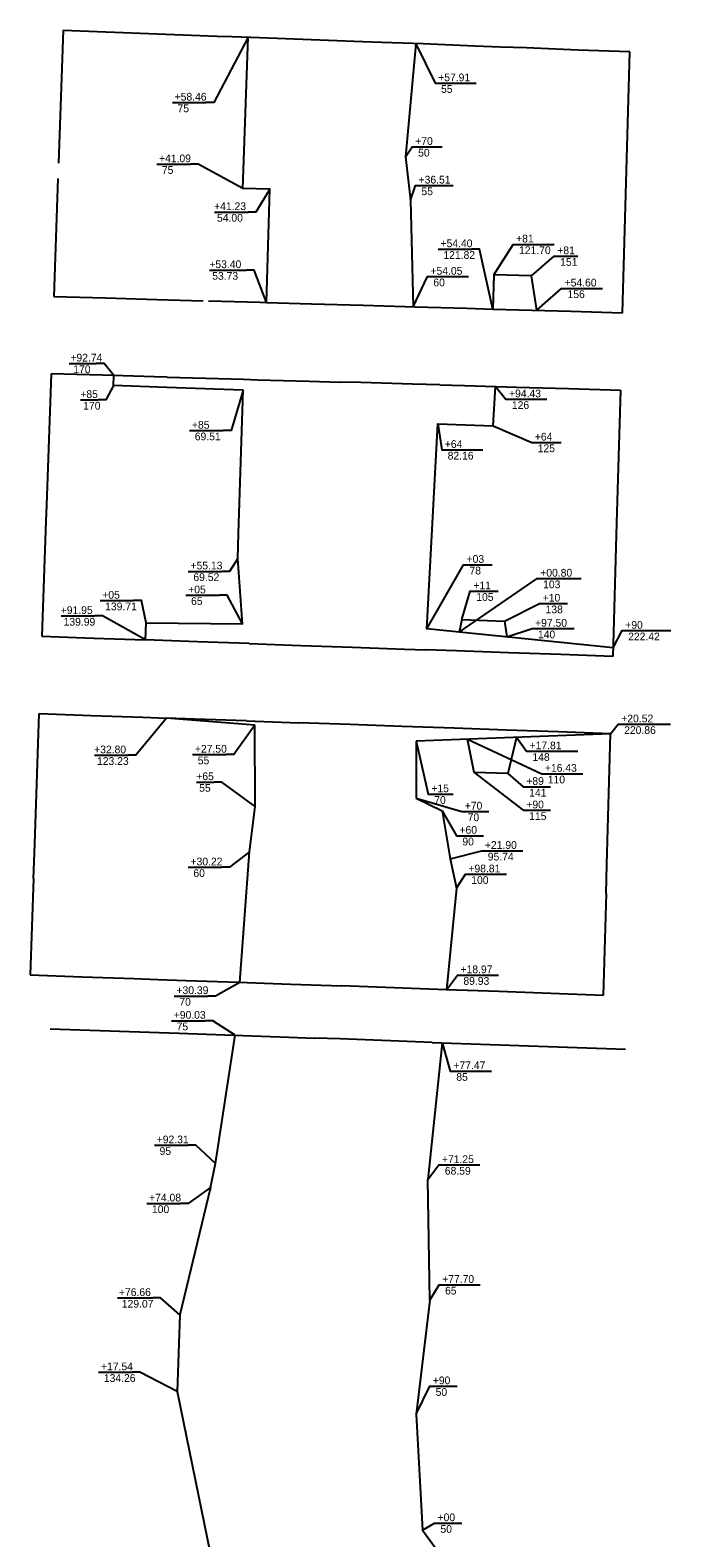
# Model space of a CAD drawing. Extents: x 979729 to 993523, y 1834148 to 1845433.
# Drawn here: x 992244 to 992740, y 1841951 to 1843120 of the extents above; entities that cross this region are included whole.
import ezdxf

# ---------------------------------------------------------------- set-up
doc = ezdxf.new("R2010")
doc.units = 0
for name, color, linetype in [('51', 7, 'Continuous'), ('53', 7, 'Continuous'), ('R_Draft', 7, 'Continuous'), ('S_EXIST_ROW', 7, 'Continuous')]:
    doc.layers.add(name, color=color, linetype=linetype)

msp = doc.modelspace()

# ---------------------------------------------------------------- linework, layer by layer
at = {"layer": '51'}
for p, q in [((992542.5, 1843109.9), (992534.5, 1843022.2)), ((992534.5, 1843022.2), (992538.3, 1842988.6)), ((992308.2, 1842844.8), (992308.5, 1842852.6)), ((992349.5, 1842843.4), (992308.2, 1842844.8)), ((992408.7, 1842841.4), (992349.5, 1842843.4)), ((992405.2, 1842730.1), (992408.7, 1842841.4)), ((992418, 1842518.5), (992417.7, 1842581.6)), ((992693.5, 1842574.8), (992542.7, 1842569.2)), ((992542.7, 1842569.2), (992542.9, 1842524.8)), ((992693.5, 1842574.8), (992693.5, 1842574.8)), ((992693.5, 1842574.8), (992693.5, 1842574.8)), ((992542.9, 1842524.8), (992563, 1842515.1)), ((992418, 1842518.5), (992418, 1842518.5)), ((992418, 1842518.5), (992418, 1842518.5)), ((992574.1, 1842455.1), (992566.3, 1842376.4)), ((992387.4, 1842241.6), (992402.6, 1842341.1)), ((992563, 1842335.3), (992551.9, 1842229.2)), ((992383.4, 1842223.1), (992387.4, 1842241.6)), ((992383.4, 1842223.1), (992359.5, 1842124.3)), ((992359.5, 1842124.3), (992357.5, 1842065)), ((992357.5, 1842065), (992383.4, 1841938.6))]:
    msp.add_line(p, q, dxfattribs=at)
for points in [[(992426.8, 1842909.2), (992429.5, 1842997), (992408.5, 1842997.6), (992412.6, 1843114.9)], [(992542.5, 1843109.9), (992542.5, 1843109.9)], [(992538.3, 1842988.6), (992540.5, 1842906)], [(992695.4, 1842641.6), (992551.2, 1842656.1), (992559.5, 1842815.2), (992602.4, 1842813.7), (992604.4, 1842844.1)], [(992333, 1842647.6), (992333.5, 1842661), (992408.2, 1842660), (992404.6, 1842710.8), (992405.2, 1842730.1)], [(992417.7, 1842581.6), (992349.4, 1842587)], [(992406.1, 1842382.1), (992413.5, 1842483.3), (992418, 1842518.5)], [(992563, 1842515.1), (992569.3, 1842477.8), (992574.1, 1842455.1)], [(992553.3, 1842135.6), (992551.9, 1842229.2)], [(992553.3, 1842135.6), (992542.9, 1842047.2), (992547.7, 1841957.3), (992563.9, 1841935.1)]]:
    msp.add_lwpolyline(points, dxfattribs=at)
at = {"layer": '53'}
for p, q in [((992578.3, 1842663.5), (992576.1, 1842653.6)), ((992578.3, 1842663.5), (992611.2, 1842662.1)), ((992611.2, 1842662.1), (992613.1, 1842649.9))]:
    msp.add_line(p, q, dxfattribs=at)
for points in [[(992636.4, 1842903.2), (992632.3, 1842929.8), (992603.1, 1842930.8), (992602.3, 1842904.2)], [(992620.7, 1842572.1), (992613.8, 1842544), (992587.8, 1842544.8), (992582.7, 1842570.7)]]:
    msp.add_lwpolyline(points, dxfattribs=at)
at = {"layer": 'R_Draft'}
for p, q in [((992563.5, 1843079.3), (992589.3, 1843079.3)), ((992353.9, 1843064.3), (992379.9, 1843064.3)), ((992545.8, 1843029.9), (992563.1, 1843029.9)), ((992341.7, 1843016.5), (992367.8, 1843016.5)), ((992548.4, 1843000), (992571.4, 1843000)), ((992386.5, 1842979.4), (992412.6, 1842979.4)), ((992623.9, 1842954.3), (992649.8, 1842954.3)), ((992559.9, 1842950.6), (992586, 1842950.6)), ((992655.8, 1842945.2), (992668.1, 1842945.2)), ((992382.5, 1842934.4), (992411.3, 1842934.4)), ((992557.5, 1842929.3), (992583.4, 1842929.3)), ((992661.5, 1842920.2), (992687.3, 1842920.2)), ((992273.9, 1842862), (992294.9, 1842862)), ((992282.6, 1842833.7), (992296.3, 1842833.7)), ((992618.4, 1842834.2), (992644.2, 1842834.2)), ((992367.2, 1842809.9), (992393.3, 1842809.9)), ((992568.6, 1842795), (992594.5, 1842795)), ((992638.4, 1842800.7), (992655.3, 1842800.7)), ((992366.1, 1842700.8), (992392.2, 1842700.8)), ((992585.6, 1842705.9), (992601.7, 1842705.9)), ((992590.8, 1842685.4), (992606.3, 1842685.4)), ((992642.6, 1842695.2), (992670.7, 1842695.2)), ((992297.8, 1842678.1), (992323.8, 1842678.1)), ((992364.3, 1842682.2), (992390.3, 1842682.2)), ((992644.5, 1842675.8), (992660, 1842675.8)), ((992267.6, 1842666.2), (992293.6, 1842666.2)), ((992638.7, 1842656.4), (992665.3, 1842656.4)), ((992708.5, 1842654.8), (992740.2, 1842654.8)), ((992705.4, 1842582.2), (992739.9, 1842582.2)), ((992293.5, 1842558.2), (992319.6, 1842558.2)), ((992369.5, 1842558.7), (992395.6, 1842558.7)), ((992634.3, 1842561.3), (992668.1, 1842561.3)), ((992646.3, 1842543.9), (992672.1, 1842543.9)), ((992372.6, 1842537.4), (992386.2, 1842537.4)), ((992631.8, 1842533.7), (992646.9, 1842533.7)), ((992558.2, 1842528), (992571.4, 1842528)), ((992584.1, 1842514.6), (992599.2, 1842514.6)), ((992631.8, 1842515.5), (992646.9, 1842515.5)), ((992580, 1842495.8), (992595.1, 1842495.8)), ((992599.7, 1842484.1), (992625.5, 1842484.1)), ((992366.1, 1842471.3), (992392.2, 1842471.3)), ((992587, 1842465.9), (992612.8, 1842465.9)), ((992580.8, 1842387.7), (992606.7, 1842387.7)), ((992355.2, 1842371.5), (992381.2, 1842371.5)), ((992353.2, 1842352.4), (992379.2, 1842352.4)), ((992575.3, 1842313.3), (992601.2, 1842313.3)), ((992340, 1842255.8), (992366, 1842255.8)), ((992566.4, 1842240.5), (992592.2, 1842240.5)), ((992334, 1842210.7), (992360.1, 1842210.7)), ((992566.6, 1842147.6), (992592.4, 1842147.6)), ((992311.4, 1842137.4), (992338.7, 1842137.4)), ((992296.7, 1842079.8), (992322.7, 1842079.8)), ((992559.3, 1842069), (992574.5, 1842069)), ((992563, 1841962.8), (992578.1, 1841962.8))]:
    msp.add_line(p, q, dxfattribs=at)
for points in [[(992412.6, 1843114.9), (992385.9, 1843064.3), (992379.9, 1843064.3)], [(992542.5, 1843109.9), (992557.5, 1843079.3), (992563.5, 1843079.3)], [(992534.5, 1843022.2), (992539.8, 1843029.9), (992545.8, 1843029.9)], [(992408.5, 1842997.6), (992373.8, 1843016.5), (992367.8, 1843016.5)], [(992538.3, 1842988.6), (992542.4, 1843000), (992548.4, 1843000)], [(992429.5, 1842997), (992418.6, 1842979.4), (992412.6, 1842979.4)], [(992603.1, 1842930.8), (992617.9, 1842954.3), (992623.9, 1842954.3)], [(992602.3, 1842904.2), (992592, 1842950.6), (992586, 1842950.6)], [(992632.3, 1842929.8), (992649.8, 1842945.2), (992655.8, 1842945.2)], [(992426.8, 1842909.2), (992417.3, 1842934.4), (992411.3, 1842934.4)], [(992540.5, 1842906), (992551.5, 1842929.3), (992557.5, 1842929.3)], [(992636.4, 1842903.2), (992655.5, 1842920.2), (992661.5, 1842920.2)], [(992308.5, 1842852.6), (992300.9, 1842862), (992294.9, 1842862)], [(992308.2, 1842844.8), (992302.3, 1842833.7), (992296.3, 1842833.7)], [(992408.7, 1842841.4), (992399.3, 1842809.9), (992393.3, 1842809.9)], [(992604.4, 1842844.1), (992612.4, 1842834.2), (992618.4, 1842834.2)], [(992559.5, 1842815.2), (992562.6, 1842795), (992568.6, 1842795)], [(992602.4, 1842813.7), (992632.4, 1842800.7), (992638.4, 1842800.7)], [(992404.6, 1842710.8), (992398.2, 1842700.8), (992392.2, 1842700.8)], [(992551.2, 1842656.1), (992579.6, 1842705.9), (992585.6, 1842705.9)], [(992576.1, 1842653.6), (992636.6, 1842695.2), (992642.6, 1842695.2)], [(992578.3, 1842663.5), (992584.8, 1842685.4), (992590.8, 1842685.4)], [(992333.5, 1842661), (992329.8, 1842678.1), (992323.8, 1842678.1)], [(992408.2, 1842660), (992396.3, 1842682.2), (992390.3, 1842682.2)], [(992611.2, 1842662.1), (992638.5, 1842675.8), (992644.5, 1842675.8)], [(992333, 1842647.6), (992299.6, 1842666.2), (992293.6, 1842666.2)], [(992613.1, 1842649.9), (992632.7, 1842656.4), (992638.7, 1842656.4)], [(992695.4, 1842641.6), (992702.5, 1842654.8), (992708.5, 1842654.8)], [(992349.4, 1842587), (992325.6, 1842558.2), (992319.6, 1842558.2)], [(992417.7, 1842581.6), (992401.6, 1842558.7), (992395.6, 1842558.7)], [(992693.5, 1842574.8), (992699.4, 1842582.2), (992705.4, 1842582.2)], [(992542.7, 1842569.2), (992552.2, 1842528), (992558.2, 1842528)], [(992582.7, 1842570.7), (992640.3, 1842543.9), (992646.3, 1842543.9)], [(992620.7, 1842572.1), (992628.3, 1842561.3), (992634.3, 1842561.3)], [(992587.8, 1842544.8), (992625.8, 1842515.5), (992631.8, 1842515.5)], [(992613.8, 1842544), (992625.8, 1842533.7), (992631.8, 1842533.7)], [(992418, 1842518.5), (992392.2, 1842537.4), (992386.2, 1842537.4)], [(992542.9, 1842524.8), (992578.1, 1842514.6), (992584.1, 1842514.6)], [(992563, 1842515.1), (992574, 1842495.8), (992580, 1842495.8)], [(992413.5, 1842483.3), (992398.2, 1842471.3), (992392.2, 1842471.3)], [(992569.3, 1842477.8), (992593.7, 1842484.1), (992599.7, 1842484.1)], [(992574.1, 1842455.1), (992581, 1842465.9), (992587, 1842465.9)], [(992406.1, 1842382.1), (992387.2, 1842371.5), (992381.2, 1842371.5)], [(992566.3, 1842376.4), (992574.8, 1842387.7), (992580.8, 1842387.7)], [(992402.6, 1842341.1), (992385.2, 1842352.4), (992379.2, 1842352.4)], [(992563, 1842335.3), (992569.3, 1842313.3), (992575.3, 1842313.3)], [(992387.4, 1842241.6), (992372, 1842255.8), (992366, 1842255.8)], [(992551.9, 1842229.2), (992560.4, 1842240.5), (992566.4, 1842240.5)], [(992383.4, 1842223.1), (992366.1, 1842210.7), (992360.1, 1842210.7)], [(992553.3, 1842135.6), (992560.6, 1842147.6), (992566.6, 1842147.6)], [(992359.5, 1842124.3), (992344.7, 1842137.4), (992338.7, 1842137.4)], [(992357.5, 1842065), (992328.7, 1842079.8), (992322.7, 1842079.8)], [(992542.9, 1842047.2), (992553.3, 1842069), (992559.3, 1842069)], [(992547.7, 1841957.3), (992557, 1841962.8), (992563, 1841962.8)]]:
    msp.add_lwpolyline(points, dxfattribs=at)
at = {"layer": 'S_EXIST_ROW'}
for p, q in [((992269.1, 1843120.4), (992265.5, 1843017.2)), ((992269.1, 1843120.4), (992308.9, 1843118.9)), ((992308.9, 1843118.9), (992348.7, 1843117.3)), ((992348.7, 1843117.3), (992388.5, 1843115.8)), ((992388.5, 1843115.8), (992393.2, 1843115.6)), ((992428.3, 1843114.3), (992393.2, 1843115.6)), ((992468.2, 1843112.7), (992428.3, 1843114.3)), ((992508.1, 1843111.2), (992468.2, 1843112.7)), ((992548.2, 1843109.7), (992508.1, 1843111.2)), ((992588.3, 1843108.1), (992548.2, 1843109.7)), ((992608.3, 1843107.3), (992588.3, 1843108.1)), ((992628.4, 1843106.6), (992608.3, 1843107.3)), ((992668.4, 1843105), (992628.4, 1843106.6)), ((992708.5, 1843103.5), (992668.4, 1843105)), ((992705.6, 1843002.4), (992708.5, 1843103.5)), ((992265.1, 1843005.5), (992261.9, 1842913.9)), ((992702.8, 1842901.3), (992705.6, 1843002.4)), ((992261.9, 1842913.9), (992301.9, 1842912.8)), ((992301.9, 1842912.8), (992341.8, 1842911.6)), ((992341.8, 1842911.6), (992377.8, 1842910.6)), ((992381.8, 1842910.5), (992421.8, 1842909.4)), ((992421.8, 1842909.4), (992426.8, 1842909.2)), ((992426.8, 1842909.2), (992461.8, 1842908.2)), ((992461.8, 1842908.2), (992501.8, 1842907.1)), ((992501.8, 1842907.1), (992542, 1842905.9)), ((992542, 1842905.9), (992582.2, 1842904.8)), ((992582.2, 1842904.8), (992602.3, 1842904.2)), ((992602.3, 1842904.2), (992622.4, 1842903.6)), ((992622.4, 1842903.6), (992662.6, 1842902.5)), ((992662.6, 1842902.5), (992702.8, 1842901.3)), ((992259.8, 1842854), (992256.3, 1842752.2)), ((992299.8, 1842852.8), (992259.8, 1842854)), ((992339.8, 1842851.7), (992299.8, 1842852.8)), ((992349.8, 1842851.4), (992339.8, 1842851.7)), ((992349.8, 1842851.4), (992379.9, 1842850.5)), ((992379.9, 1842850.5), (992408.9, 1842849.7)), ((992408.9, 1842849.7), (992419.9, 1842849.4)), ((992419.9, 1842849.4), (992459.9, 1842848.2)), ((992459.9, 1842848.2), (992483.9, 1842847.6)), ((992499.9, 1842847.1), (992483.9, 1842847.6)), ((992540.1, 1842846), (992499.9, 1842847.1)), ((992561.1, 1842845.4), (992540.1, 1842846)), ((992561.1, 1842845.4), (992580.4, 1842844.8)), ((992580.4, 1842844.8), (992620.6, 1842843.7)), ((992620.6, 1842843.7), (992660.8, 1842842.5)), ((992660.8, 1842842.5), (992701.1, 1842841.4)), ((992701.1, 1842841.4), (992698.1, 1842738.1)), ((992256.3, 1842752.2), (992255.8, 1842740)), ((992255.8, 1842740), (992252.7, 1842650.5)), ((992698.1, 1842738.1), (992695.2, 1842634.8)), ((992252.7, 1842650.5), (992292.9, 1842649.1)), ((992292.9, 1842649.1), (992333, 1842647.6)), ((992373.2, 1842646.2), (992333, 1842647.6)), ((992413.4, 1842644.8), (992373.2, 1842646.2)), ((992413.4, 1842644.8), (992453.5, 1842643.4)), ((992453.5, 1842643.4), (992477.5, 1842642.5)), ((992477.5, 1842642.5), (992493.5, 1842642)), ((992493.5, 1842642), (992533.8, 1842640.5)), ((992533.8, 1842640.5), (992550.3, 1842640)), ((992574.2, 1842639.1), (992550.3, 1842640)), ((992614.5, 1842637.7), (992574.2, 1842639.1)), ((992654.9, 1842636.2), (992614.5, 1842637.7)), ((992695.2, 1842634.8), (992654.9, 1842636.2)), ((992247.1, 1842489.2), (992250.6, 1842590.5)), ((992250.6, 1842590.5), (992290.8, 1842589.1)), ((992290.8, 1842589.1), (992331, 1842587.7)), ((992331, 1842587.7), (992349.4, 1842587)), ((992371.2, 1842586.3), (992349.4, 1842587)), ((992411.4, 1842584.8), (992371.2, 1842586.3)), ((992411.4, 1842584.8), (992438.4, 1842583.9)), ((992438.4, 1842583.9), (992451.7, 1842583.4)), ((992491.6, 1842582), (992451.7, 1842583.4)), ((992504.8, 1842581.5), (992491.6, 1842582)), ((992532, 1842580.6), (992504.8, 1842581.5)), ((992572.4, 1842579.1), (992532, 1842580.6)), ((992612.8, 1842577.7), (992572.4, 1842579.1)), ((992653.1, 1842576.3), (992612.8, 1842577.7)), ((992693.5, 1842574.8), (992653.1, 1842576.3)), ((992690.6, 1842473.4), (992693.5, 1842574.8)), ((992246.2, 1842462.6), (992247.1, 1842489.2)), ((992246.2, 1842462.6), (992245.7, 1842447.9)), ((992690, 1842451), (992690.6, 1842473.4)), ((992690, 1842451), (992687.8, 1842372)), ((992245.7, 1842447.9), (992243.6, 1842388)), ((992243.6, 1842388), (992284, 1842386.5)), ((992284, 1842386.5), (992324.3, 1842385.1)), ((992324.3, 1842385.1), (992342.6, 1842384.4)), ((992342.6, 1842384.4), (992364.6, 1842383.6)), ((992364.6, 1842383.6), (992405, 1842382.2)), ((992405, 1842382.2), (992432, 1842381.2)), ((992432, 1842381.2), (992445.3, 1842380.7)), ((992445.3, 1842380.7), (992485.3, 1842379.3)), ((992525.8, 1842377.8), (992485.3, 1842379.3)), ((992566.3, 1842376.4), (992525.8, 1842377.8)), ((992606.8, 1842374.9), (992566.3, 1842376.4)), ((992647.3, 1842373.5), (992606.8, 1842374.9)), ((992687.8, 1842372), (992647.3, 1842373.5)), ((992259.2, 1842346.2), (992359.1, 1842342.7)), ((992359.1, 1842342.7), (992444, 1842339.6)), ((992444, 1842339.6), (992464, 1842338.9)), ((992484, 1842338.2), (992464, 1842338.9)), ((992555.1, 1842335.6), (992484, 1842338.2)), ((992555.1, 1842335.6), (992705, 1842330.2))]:
    msp.add_line(p, q, dxfattribs=at)

# ---------------------------------------------------------------- texts
at = {"layer": 'R_Draft'}
for s, p in [('+57.91', (992559.9, 1843080.8)), ('+58.46', (992355.6, 1843065.8)), (' 55', (992559.9, 1843071.8)), (' 75', (992355.6, 1843056.8)), ('+70', (992542.1, 1843031.4)), ('+41.09', (992343.5, 1843018)), (' 50', (992542.1, 1843022.4)), (' 75', (992343.5, 1843009)), ('+36.51', (992544.7, 1843001.5)), (' 55', (992544.7, 1842992.5)), ('+41.23', (992386.2, 1842980.9)), (' 54.00', (992386.2, 1842971.9)), ('+54.40', (992561.7, 1842952.1)), ('+81', (992620.3, 1842955.8)), ('+53.40', (992382.5, 1842935.9)), (' 121.82', (992561.7, 1842943.1)), (' 121.70', (992620.3, 1842946.8)), ('+81', (992652.2, 1842946.7)), (' 151', (992652.2, 1842937.7)), (' 53.73', (992382.5, 1842926.9)), ('+54.05', (992553.9, 1842930.8)), (' 60', (992553.9, 1842921.8)), ('+54.60', (992657.9, 1842921.7)), (' 156', (992657.9, 1842912.7)), ('+92.74', (992274.8, 1842863.5)), (' 170', (992274.8, 1842854.5)), ('+85', (992282.5, 1842835.2)), ('+94.43', (992614.8, 1842835.7)), (' 170', (992282.5, 1842826.2)), (' 126', (992614.8, 1842826.7)), ('+85', (992369, 1842811.4)), (' 69.51', (992369, 1842802.4)), ('+64', (992565, 1842796.5)), ('+64', (992634.8, 1842802.2)), (' 82.16', (992565, 1842787.5)), (' 125', (992634.8, 1842793.2)), ('+55.13', (992367.9, 1842702.3)), ('+03', (992581.9, 1842707.4)), (' 69.52', (992367.9, 1842693.3)), (' 78', (992581.9, 1842698.4)), ('+00.80', (992639, 1842696.7)), ('+05', (992299.5, 1842679.6)), ('+05', (992366.1, 1842683.7)), ('+11', (992587.2, 1842686.9)), (' 103', (992639, 1842687.7)), ('+91.95', (992267.3, 1842667.7)), (' 139.71', (992299.5, 1842670.6)), (' 65', (992366.1, 1842674.7)), (' 105', (992587.2, 1842677.9)), ('+10', (992640.9, 1842677.3)), (' 138', (992640.9, 1842668.3)), (' 139.99', (992267.3, 1842658.7)), ('+97.50', (992635, 1842657.9)), ('+90', (992704.9, 1842656.3)), (' 140', (992635, 1842648.9)), (' 222.42', (992704.9, 1842647.3)), ('+20.52', (992701.8, 1842583.7)), (' 220.86', (992701.8, 1842574.7)), ('+17.81', (992630.7, 1842562.8)), ('+32.80', (992293.2, 1842559.7)), (' 123.23', (992293.2, 1842550.7)), ('+27.50', (992371.3, 1842560.2)), (' 55', (992371.3, 1842551.2)), (' 148', (992630.7, 1842553.8)), ('+65', (992372.4, 1842538.9)), ('+16.43', (992642.6, 1842545.4)), (' 55', (992372.4, 1842529.9)), ('+15', (992554.6, 1842529.5)), ('+89', (992628.2, 1842535.2)), (' 110', (992642.6, 1842536.4)), (' 70', (992554.6, 1842520.5)), ('+70', (992580.5, 1842516.1)), ('+90', (992628.2, 1842517)), (' 141', (992628.2, 1842526.2)), (' 70', (992580.5, 1842507.1)), (' 115', (992628.2, 1842508)), ('+60', (992576.4, 1842497.3)), (' 90', (992576.4, 1842488.3)), ('+21.90', (992596.1, 1842485.6)), ('+30.22', (992367.9, 1842472.8)), (' 95.74', (992596.1, 1842476.6)), (' 60', (992367.9, 1842463.8)), ('+98.81', (992583.3, 1842467.4)), (' 100', (992583.3, 1842458.4)), ('+18.97', (992577.2, 1842389.2)), (' 89.93', (992577.2, 1842380.2)), ('+30.39', (992357, 1842373)), (' 70', (992357, 1842364)), ('+90.03', (992354.9, 1842353.9)), (' 75', (992354.9, 1842344.9)), ('+77.47', (992571.7, 1842314.8)), (' 85', (992571.7, 1842305.8)), ('+92.31', (992341.7, 1842257.3)), (' 95', (992341.7, 1842248.3)), ('+71.25', (992562.8, 1842242)), (' 68.59', (992562.8, 1842233)), ('+74.08', (992335.8, 1842212.2)), (' 100', (992335.8, 1842203.2)), ('+77.70', (992563, 1842149.1)), ('+76.66', (992312.4, 1842138.9)), (' 129.07', (992312.4, 1842129.9)), (' 65', (992563, 1842140.1)), ('+17.54', (992298.5, 1842081.3)), (' 134.26', (992298.5, 1842072.3)), ('+90', (992555.7, 1842070.5)), (' 50', (992555.7, 1842061.5)), ('+00', (992559.4, 1841964.3)), (' 50', (992559.4, 1841955.3))]:
    msp.add_text(s, height=6, rotation=360, dxfattribs=at).set_placement(p)

doc.saveas('drawing.dxf')
